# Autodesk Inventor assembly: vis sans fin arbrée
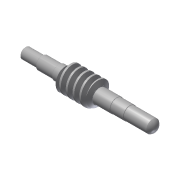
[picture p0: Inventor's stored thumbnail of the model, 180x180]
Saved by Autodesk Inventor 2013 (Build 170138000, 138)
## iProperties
Created: 2011-07
Part Number: vis sans fin arbrée
Document SubType Name: Assembly
Designer: Laur
Author: Laur
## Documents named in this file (3)
- D:\_an13-14\FORMULAIRE_2014\Sujet E4 Poissy 2014\Modélisation_7970_shimano_2014\pièces mobile vis sans fin\vis sans fin arbrée.iam
- D:\_an13-14\FORMULAIRE_2014\Sujet E4 Poissy 2014\Modélisation_7970_shimano_2014\pièces mobile vis sans fin\vis sans fin.ipt
- D:\_an13-14\FORMULAIRE_2014\Sujet E4 Poissy 2014\Modélisation_7970_shimano_2014\vis sans fin arbrée\Design Accelerator\Engrenages à vis sans fin1.iam
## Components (2 placed, 2 different names)
1. vis sans fin:1 — Placage:1, Affleurement:1
2. Engrenages à vis sans fin:1 [sub-assembly] — Placage:1, Affleurement:1
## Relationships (2: Mate 1, Flush 1)
- Placage:1 [Mate]: vis sans fin:1 ↔ Engrenages à vis sans fin:1
- Affleurement:1 [Flush]: vis sans fin:1 ↔ Engrenages à vis sans fin:1
